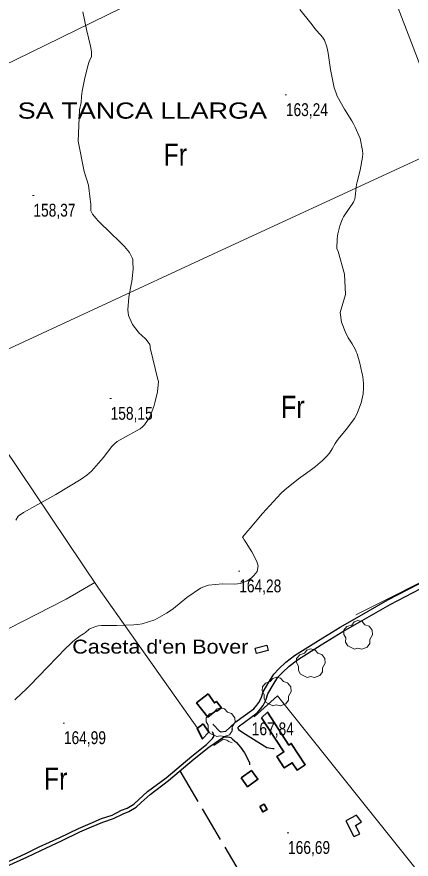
# Model space of a CAD drawing. Extents: x -807245 to 6129983, y -54972206 to 262146364.
# Drawn here: x 490559 to 490827, y 4382866 to 4383439 of the extents above; entities that cross this region are included whole.
import ezdxf
from ezdxf.enums import TextEntityAlignment as Align

# ---------------------------------------------------------------- set-up
doc = ezdxf.new("R2010")
doc.units = 0
doc.header["$LTSCALE"] = 4
doc.linetypes.add('LONG_DASHED', pattern=[7.5, 6, -1.5])
doc.linetypes.add('MEDIUM_DASHED', pattern=[4.5, 3, -1.5])
for name, color, linetype, lineweight in [('25', 7, 'LONG_DASHED', 25), ('27', 7, 'Continuous', 25), ('29', 7, 'Continuous', 13), ('38', 7, 'Continuous', 25), ('47', 7, 'Continuous', 35), ('48', 7, 'MEDIUM_DASHED', 25), ('51', 7, 'Continuous', 13), ('7', 7, 'Continuous', 13), ('9', 7, 'Continuous', 13)]:
    doc.layers.add(name, color=color, linetype=linetype, lineweight=lineweight)
doc.layers.add('31', color=7, linetype='Continuous')
doc.layers.add('5', color=7, linetype='Continuous')

msp = doc.modelspace()

# ---------------------------------------------------------------- linework, layer by layer
at = {"layer": '25'}
msp.add_lwpolyline([(490669.9, 4382926.29), (490710.05, 4382857.96), (490757.04, 4382781.42), (490841.49, 4382845.71)], dxfattribs=at)
at = {"layer": '27'}
msp.add_spline([(491255.21, 4383970.03), (491244.34, 4383967.52), (491230.36, 4383957.66), (491230.81, 4383957.81), (491230.81, 4383957.81), (491220.15, 4383951.47), (491212.7, 4383943.01), (491205.06, 4383944.23), (491184.85, 4383957.71), (491152.82, 4383981.27), (491128.36, 4384004.58), (491128.29, 4384004.88), (491122.26, 4384021.39), (491095.75, 4384034.59), (491071.07, 4384059.32), (491064.71, 4384065.12)], degree=3, dxfattribs=at)
at = {"layer": '29'}
for points in [[(490788.49, 4383009.19), (490783.95, 4383011.31), (490782.54, 4383013.85), (490782.64, 4383016.83), (490781.27, 4383019.24), (490781.31, 4383021.99), (490783.47, 4383024.59), (490786.66, 4383025.59), (490788.31, 4383027.78), (490790.88, 4383028.61), (490793.74, 4383027.96), (490795.69, 4383025.69), (490798.5, 4383024.87), (490800.63, 4383022.02), (490800.87, 4383018.89), (490798.99, 4383015.74), (490798.99, 4383013.06), (490797.17, 4383010.45), (490793.55, 4383009.11), (490790.78, 4383009.74)], [(490756.34, 4382989.94), (490751.8, 4382992.06), (490750.39, 4382994.6), (490750.49, 4382997.58), (490749.12, 4382999.99), (490749.16, 4383002.74), (490751.32, 4383005.34), (490754.51, 4383006.34), (490756.16, 4383008.53), (490758.73, 4383009.36), (490761.59, 4383008.71), (490763.54, 4383006.44), (490766.35, 4383005.62), (490768.48, 4383002.77), (490768.72, 4382999.64), (490766.84, 4382996.49), (490766.84, 4382993.81), (490765.02, 4382991.2), (490761.4, 4382989.86), (490758.63, 4382990.49)], [(490733.11, 4382970.66), (490728.57, 4382972.78), (490727.16, 4382975.32), (490727.26, 4382978.3), (490725.89, 4382980.71), (490725.93, 4382983.46), (490728.09, 4382986.06), (490731.28, 4382987.06), (490732.93, 4382989.25), (490735.5, 4382990.08), (490738.36, 4382989.43), (490740.31, 4382987.16), (490743.12, 4382986.34), (490745.25, 4382983.49), (490745.49, 4382980.36), (490743.61, 4382977.21), (490743.61, 4382974.53), (490741.79, 4382971.92), (490738.17, 4382970.58), (490735.4, 4382971.21)], [(490694.96, 4382949.71), (490690.42, 4382951.83), (490689.01, 4382954.37), (490689.11, 4382957.35), (490687.74, 4382959.76), (490687.78, 4382962.51), (490689.94, 4382965.11), (490693.13, 4382966.11), (490694.78, 4382968.3), (490697.35, 4382969.13), (490700.21, 4382968.48), (490702.16, 4382966.21), (490704.97, 4382965.39), (490707.1, 4382962.54), (490707.34, 4382959.41), (490705.46, 4382956.26), (490705.46, 4382953.58), (490703.64, 4382950.97), (490700.02, 4382949.63), (490697.25, 4382950.26)]]:
    msp.add_lwpolyline(points, close=True, dxfattribs=at)
at = {"layer": '38'}
for points in [[(490709.37, 4382956.35), (490722.41, 4382965.9), (490724.86, 4382968.74), (490726.52, 4382970.89), (490728.35, 4382974.53), (490729.62, 4382978.74), (490733.25, 4382984.93), (490736.44, 4382990.04), (490739.55, 4382993.28), (490744.18, 4382997.58), (490749.81, 4383001.94), (490765.95, 4383012.18), (490780.69, 4383021.17), (490792.17, 4383027.65), (490812.86, 4383039.57), (490833.8, 4383050.34), (490847.16, 4383056.48), (490854.06, 4383059.35), (490857.69, 4383060.66), (490861.03, 4383061.73), (490862.93, 4383062.09)], [(490707.3, 4382959.18), (490720.02, 4382968.49), (490722.15, 4382970.96), (490723.54, 4382972.77), (490725.09, 4382975.83), (490726.39, 4382980.15), (490730.25, 4382986.74), (490733.66, 4382992.2), (490737.09, 4382995.78), (490741.91, 4383000.26), (490747.8, 4383004.82), (490764.1, 4383015.16), (490778.92, 4383024.2), (490790.43, 4383030.69), (490811.19, 4383042.65), (490832.26, 4383053.49)], [(490707.37, 4382959.23), (490700.77, 4382953.04), (490697.99, 4382952.67), (490696.94, 4382953.05), (490692.16, 4382958.17)], [(490692.09, 4382948.3), (490692.96, 4382949.77), (490692.81, 4382950.89), (490692.59, 4382951.34), (490691.92, 4382952.92)], [(490708.95, 4382956.09), (490709.77, 4382954.44), (490712.61, 4382952.56), (490728.93, 4382942.23), (490732.98, 4382941.55), (490733.95, 4382941.47)], [(490533.62, 4382857.25), (490538.85, 4382859.42), (490551.14, 4382863.81), (490564.67, 4382869.96), (490574.19, 4382874.58), (490588.16, 4382881.14), (490600.8, 4382887.18), (490608.78, 4382890.54), (490616.64, 4382893.92), (490623.8, 4382896.21), (490630.21, 4382899.53), (490634.01, 4382901.09), (490638.56, 4382903.81), (490641.78, 4382906.72), (490647.91, 4382912.36), (490660.56, 4382921.71), (490677.91, 4382936.42), (490687.95, 4382944.31), (490692.09, 4382948.3)], [(490552.09, 4382861.45), (490565.75, 4382867.66), (490575.29, 4382872.28), (490589.25, 4382878.84), (490601.84, 4382884.86), (490609.78, 4382888.2), (490617.53, 4382891.53), (490624.78, 4382893.85), (490631.28, 4382897.22), (490635.15, 4382898.81), (490640.08, 4382901.76), (490643.49, 4382904.84), (490649.54, 4382910.39), (490662.14, 4382919.72), (490679.52, 4382934.45), (490689.62, 4382942.39), (490699.78, 4382949.59)], [(490699.78, 4382949.59), (490702.63, 4382949.44), (490704.58, 4382948.98), (490705.63, 4382947.93), (490708.24, 4382945.67), (490711.01, 4382942.51), (490713.85, 4382938.68), (490717.2, 4382932), (490717.12, 4382930.57)]]:
    msp.add_lwpolyline(points, dxfattribs=at)
at = {"layer": '47'}
for points in [[(490689.07, 4382978.87), (490681.18, 4382972.67), (490688.79, 4382962.96), (490694.47, 4382967.43), (490694.9, 4382966.86), (490698.05, 4382969.24), (490694.7, 4382973.65), (490693.31, 4382972.59)], [(490725.39, 4382962.49), (490740.54, 4382939.2), (490735.76, 4382936.09), (490740.8, 4382928.33), (490746.24, 4382931.88), (490749.51, 4382926.85), (490755.07, 4382930.47), (490745.61, 4382944.99), (490743.86, 4382943.86), (490729.31, 4382966.39)], [(490685.71, 4382958.41), (490689.52, 4382952.7), (490685.23, 4382948.06), (490681.58, 4382955.12)], [(490711.47, 4382921.59), (490718.49, 4382926.68), (490722.86, 4382920.66), (490715.84, 4382915.57)], [(490724.16, 4382902.13), (490726.23, 4382898.39), (490729.18, 4382900.02), (490727.11, 4382903.76)]]:
    msp.add_lwpolyline(points, close=True, dxfattribs=at)
at = {"layer": '48'}
for points in [[(490729.95, 4383008.29), (490721.86, 4383006.25), (490720.96, 4383009.81), (490729.05, 4383011.85)], [(490790.05, 4382896.24), (490782.69, 4382892.43), (490788.29, 4382881.6), (490792.11, 4382883.58), (490789.16, 4382889.24), (490793.41, 4382891.65)]]:
    msp.add_lwpolyline(points, close=True, dxfattribs=at)
at = {"layer": '51'}
for points in [[(490666.52, 4383455.81), (490641.01, 4383450.71), (490558.11, 4383410.17), (490418.07, 4383342.51), (490291.36, 4383533.68)], [(490804.59, 4383480.92), (490854.18, 4383351.92), (490935.64, 4383138.36), (490957.63, 4383144.89), (490958.09, 4383149.91)], [(490516.49, 4383196.4), (490698.53, 4383280.71), (490854.26, 4383352.67), (491002.47, 4383418.2), (491115.97, 4383473.26)], [(490419.21, 4383343.06), (490479.51, 4383253.25), (490516.98, 4383195.63), (490614.39, 4383050.7), (490681.91, 4382955.38)], [(490934.69, 4383140.87), (490899.77, 4383128.12), (490902.3, 4383097.59), (490893.45, 4383097.39), (490886.33, 4383096.14), (490878.97, 4383092.86), (490869.96, 4383088.47), (490864.99, 4383083.98), (490860.63, 4383077.32), (490854.59, 4383065.27), (490789.41, 4383032.55)], [(490410.26, 4382941.17), (490487.48, 4382986.68), (490543.13, 4383017.92), (490592.47, 4383043.12), (490611.91, 4383054.4)], [(490720.29, 4382963.03), (490736.16, 4382977.45), (490848.58, 4382836.83), (490979.11, 4382907.36)], [(490692.87, 4382943.69), (490699.33, 4382947.95), (490701.73, 4382947.34), (490703.15, 4382946.36), (490705.39, 4382945.38)]]:
    msp.add_lwpolyline(points, dxfattribs=at)
at = {"layer": '7'}
for p, q in [((490741.39, 4383386.15), (490742.39, 4383386.15)), ((490569.71, 4383317.76), (490570.71, 4383317.76)), ((490622.22, 4383179.57), (490623.22, 4383179.57)), ((490709.67, 4383062.18), (490710.67, 4383062.18)), ((490590.44, 4382958.92), (490591.44, 4382958.92)), ((490704.92, 4382954.68), (490705.92, 4382954.68)), ((490742.87, 4382884.23), (490743.87, 4382884.23))]:
    msp.add_line(p, q, dxfattribs=at)
at = {"layer": '9'}
for points in [[(490777.41, 4383279.77), (490776.47, 4383281.65), (490776.89, 4383288.4), (490777.1, 4383290.12), (490777.35, 4383291.76), (490778.59, 4383297.13), (490780.49, 4383301.94), (490781.16, 4383303.23), (490781.9, 4383304.51), (490785.06, 4383309), (490787.89, 4383313.2), (490788.41, 4383314.29), (490788.82, 4383315.36), (490789.34, 4383318.99), (490789.68, 4383323.54), (490789.98, 4383325.18), (490790.36, 4383327), (490792.48, 4383334.95), (490794.1, 4383343.77), (490794.17, 4383346.12), (490794.07, 4383348.45), (490792.37, 4383356.53), (490789.04, 4383364.37), (490787.93, 4383366.53), (490786.73, 4383368.68), (490781.71, 4383376.44), (490776.89, 4383385.27), (490775.82, 4383388.11), (490774.86, 4383391.12), (490772.34, 4383403.39), (490770.63, 4383414.59), (490770.18, 4383416.93), (490769.74, 4383418.93), (490768.24, 4383423.38), (490766.81, 4383425.49), (490766.41, 4383426.01), (490766.02, 4383426.51), (490764.59, 4383428.08), (490761.71, 4383431.41), (490760.4, 4383433.01), (490758.87, 4383434.91), (490751.48, 4383444.23)], [(490652.82, 4383176.8), (490654.72, 4383184.3), (490655.24, 4383191.18), (490654.93, 4383192.7), (490649.57, 4383214.07), (490649.53, 4383215.34), (490649.3, 4383216.5), (490647.01, 4383219.78), (490643.47, 4383222.9), (490642.47, 4383223.96), (490641.45, 4383225.1), (490637.69, 4383229.92), (490634.97, 4383236.04), (490634.61, 4383238.01), (490634.42, 4383240.09), (490635.17, 4383248.58), (490636.75, 4383257.14), (490637.08, 4383259.26), (490637.38, 4383261.28), (490638.08, 4383267.69), (490637.95, 4383272.9), (490637.73, 4383274.17), (490637.41, 4383275.35), (490635.59, 4383278.98), (490632.1, 4383283), (490630.74, 4383284.42), (490629.21, 4383285.99), (490622.24, 4383292.77), (490615.5, 4383299.34), (490614.11, 4383300.77), (490612.93, 4383302.02), (490610.37, 4383305.15), (490609.47, 4383306.95), (490609.33, 4383307.36), (490609.24, 4383307.74), (490609.29, 4383308.83), (490609.27, 4383311.8), (490609.13, 4383313.37), (490608.93, 4383315.25), (490607.73, 4383324.76), (490604.85, 4383334.19), (490600.63, 4383354.84), (490601.68, 4383376.07), (490602.74, 4383380.96), (490602.85, 4383385.13), (490603.08, 4383386.84), (490603.4, 4383388.8), (490605.27, 4383397.9), (490607.42, 4383406.59), (490607.91, 4383408.29), (490608.36, 4383409.69), (490609.62, 4383412.17), (490609.69, 4383415.32), (490609.39, 4383417.13), (490608.95, 4383419.36), (490606.23, 4383430.79), (490603.87, 4383442.69)], [(490557.65, 4382974.67), (490562.68, 4382979.36), (490564.92, 4382981.59), (490567.52, 4382984.22), (490579.97, 4382997.1), (490592.37, 4383009.78), (490594.94, 4383012.29), (490597.14, 4383014.36), (490601.98, 4383018.25), (490604.38, 4383019.57), (490605.04, 4383020.04), (490605.7, 4383020.55), (490608.08, 4383022.73), (490612.42, 4383024.62), (490614.32, 4383024.95), (490616.52, 4383025.18), (490626.98, 4383025.3), (490638.49, 4383025.62), (490641.35, 4383025.98), (490644.08, 4383026.46), (490652.74, 4383029.17), (490660.81, 4383033.6), (490663.15, 4383035.15), (490665.54, 4383036.86), (490674.56, 4383044.21), (490683.95, 4383050.71), (490686.57, 4383051.87), (490689.19, 4383052.76), (490698.75, 4383053.68), (490707.15, 4383053.4), (490709.04, 4383053.54), (490710.76, 4383053.77), (490715.4, 4383055.39), (490718.55, 4383057.76), (490719.32, 4383058.46), (490720.05, 4383059.19), (490722.32, 4383061.98), (490722.98, 4383065.82), (490722.7, 4383067.21), (490722.22, 4383068.73), (490718.8, 4383075.37), (490714.98, 4383081.46), (490714.23, 4383082.63), (490713.63, 4383083.57), (490712.59, 4383085.12), (490712.49, 4383085.21), (490712.48, 4383085.23), (490712.48, 4383085.25), (490712.51, 4383085.32), (490712.59, 4383085.41), (490712.61, 4383085.43), (490712.63, 4383085.46), (490712.71, 4383085.58), (490714.78, 4383088.08), (490716.06, 4383089.61), (490717.64, 4383091.5), (490725.91, 4383101.36), (490735.91, 4383112.42), (490738.59, 4383115.07), (490741.23, 4383117.54), (490750.45, 4383124.99), (490758.43, 4383130.72), (490760.28, 4383132.12), (490761.99, 4383133.43), (490766.87, 4383137.49), (490770.22, 4383140.85), (490770.96, 4383141.72), (490771.61, 4383142.57), (490773.28, 4383145.45), (490775.46, 4383149.13), (490776.44, 4383150.5), (490777.57, 4383152), (490783.01, 4383158.69), (490788.52, 4383166.12), (490789.7, 4383168.1), (490790.73, 4383170.04), (490793.22, 4383176.77), (490794.38, 4383182.74), (490794.58, 4383184.2), (490794.72, 4383185.59), (490794.78, 4383189.9), (490794.21, 4383194.31), (490793.96, 4383195.76), (490793.66, 4383197.31), (490792.22, 4383203.73), (490790.36, 4383210.03), (490789.8, 4383211.51), (490789.21, 4383212.87), (490786.91, 4383216.84), (490784.32, 4383221.05), (490783.55, 4383222.56), (490782.75, 4383224.22), (490779.68, 4383231.5), (490778.92, 4383238.1), (490782.54, 4383250.43), (490781.81, 4383264.21), (490777.41, 4383279.77)], [(490558.22, 4383096.99), (490559.78, 4383099.69), (490563.52, 4383102.16), (490565.98, 4383103.58), (490569.07, 4383105.32), (490585.39, 4383114.27), (490602.75, 4383124.83), (490606.49, 4383127.58), (490609.77, 4383130.27), (490617.76, 4383139.34), (490623.48, 4383146.97), (490625.32, 4383148.75), (490627.28, 4383150.37), (490635.28, 4383155.02), (490642.76, 4383159.09), (490644.39, 4383160.36), (490645.83, 4383161.68), (490649.43, 4383166.94), (490651.68, 4383173.04), (490652.26, 4383174.88), (490652.82, 4383176.8)]]:
    msp.add_lwpolyline(points, dxfattribs=at)

# ---------------------------------------------------------------- texts
at = {"layer": '31', "width": 0.85}
for p in [(490666.71, 4383338.06), (490746.64, 4383166.51), (490585.33, 4382913.52)]:
    msp.add_text('Fr', height=15, dxfattribs=at).set_placement(p, align=Align.CENTER)
at = {"layer": '5'}
for s, height, width, p in [('SA TANCA LLARGA', 11, 1.25, (490729.15, 4383370.04)), ("Caseta d'en Bover", 9.5, 1.15, (490716.39, 4383006.13))]:
    msp.add_text(s, height=height, dxfattribs=dict(at, width=width)).set_placement(p, align=Align.RIGHT)
at = {"layer": '7', "width": 0.8}
for s, p in [('163,24', (490741.89, 4383371.78)), ('158,37', (490570.21, 4383303.39)), ('158,15', (490622.72, 4383165.2)), ('164,28', (490710.17, 4383047.81)), ('167,84', (490718.71, 4382950.56)), ('164,99', (490590.94, 4382944.55)), ('166,69', (490743.37, 4382869.86))]:
    msp.add_text(s, height=8.75, dxfattribs=at).set_placement(p)

doc.saveas('drawing.dxf')
